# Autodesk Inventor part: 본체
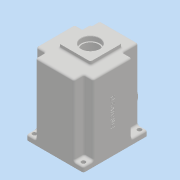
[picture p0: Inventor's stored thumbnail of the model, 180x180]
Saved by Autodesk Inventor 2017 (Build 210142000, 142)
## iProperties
Part Number: 본체
Material: 일반
Document SubType Name: Modeling
Designer: MRC
Density: 1 g/cm^3
Appearance: 기본값
Author: MRC
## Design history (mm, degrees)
sketch "스케치1"
  geometry: L1 (-49, -55)-(49, -55); L2 (49, -55)-(49, 55); L3 (49, 55)-(-49, 55); L4 (-49, 55)-(-49, -55); 3 further points
  constraints: 8 end point, 2 midpoint, 2 parallel, 1 horizontal, 1 horizontal alignment, 1 perpendicular, 1 vertical alignment
  dimensions: "d11" = 98 distance of L2.end L3.end; "d12" = 110 distance of L3.end L1.start
extrude "돌출1" new body sketch "스케치1" distance "d13" = 130; taper "d14" = 0 deg
sketch "스케치2"
  geometry: L1 (33, 28)-(49, 28); L2 (49, 28)-(49, 55); L3 (49, 55)-(33, 55); L4 (33, 55)-(33, 28); L5 (-49, 28)-(-33, 28); L6 (-33, 28)-(-33, 55); L7 (-33, 55)-(-49, 55); L8 (-49, 55)-(-49, 28); 3 further points
  constraints: 16 end point, 4 parallel, 2 coincident, 2 horizontal, 2 perpendicular
  dimensions: "d15" = 16 distance of L2.end L3.end; "d16" = 27 distance of L3.end L1.start; "d17" = 16 distance of L6.end L7.end; "d18" = 27 distance of L7.end L5.start
extrude "돌출2" cut sketch "스케치2" distance "d19" = 121; taper "d20" = 0 deg
sketch "스케치3"
  geometry: L1 (33, -55)-(49, -55); L2 (49, -55)-(49, -38); L3 (49, -38)-(33, -38); L4 (33, -38)-(33, -55); L5 (-49, -55)-(-33, -55); L6 (-33, -55)-(-33, -38); L7 (-33, -38)-(-49, -38); L8 (-49, -38)-(-49, -55); 3 further points
  constraints: 16 end point, 4 parallel, 2 coincident, 2 horizontal, 2 perpendicular
  dimensions: "d21" = 17 distance of L1.end L2.end; "d22" = 17 distance of L5.end L6.end; "d23" = 16 distance of L2.end L3.end; "d24" = 16 distance of L6.end L7.end
extrude "돌출3" cut sketch "스케치3" distance "d25" = 121; taper "d26" = 0 deg
fillet "모깎기1" dims "d27" = 3
sketch "스케치5"
  geometry: L1 (-20, 45)-(20, 45); L2 (23, 42)-(23, 33.249); L3 (-23, 33.249)-(-23, 42); L4 (46, -55)-(-46, -55) reference; L5 (-26, 42)-(-26, 33.249); L6 (26, 33.249)-(26, 42); L7 (20, 48)-(-20, 48); A1 r 42 centre (0, -5) between (-25.375, 28.468) and (25.375, 28.468); A2 r 6 centre (-29, 33.249) between (-25.375, 28.468) and (-23, 33.249); A3 r 6 centre (29, 33.249) between (23, 33.249) and (25.375, 28.468); A4 r 3 centre (-20, 42) between (-20, 45) and (-23, 42); A5 r 3 centre (20, 42) between (23, 42) and (20, 45); A6 r 3 centre (-29, 33.249) between (-27.187, 30.859) and (-26, 33.249); A7 r 45 centre (0, -5) between (-27.187, 30.859) and (27.187, 30.859); A8 r 3 centre (29, 33.249) between (26, 33.249) and (27.187, 30.859); A9 r 6 centre (20, 42) between (26, 42) and (20, 48); A10 r 6 centre (-20, 42) between (-20, 48) and (-26, 42); 6 further points
  constraints: 22 point on circle, 12 end point, 10 centre point, 8 tangent, 6 point on line, 2 equal radius, 2 parallel, 2 perpendicular, 2 vertical alignment, 1 horizontal, 1 midpoint, 7 other
  dimensions: "d39" = 46 distance of point (-23, 45) point (23, 45); "d40" = 84 diameter of A1; "d41" = 50 distance from line of L4 A1.centre; "d42" = 50 distance from line of L1 A1.centre; "d43" = 6 radius of A2 (derived); "d44" = 3 radius of A4 (derived); "d47" = 3 distance between parallel lines of L3 L5
extrude "돌출6" cut sketch "스케치5" distance "d45" = 121; taper "d46" = 0 deg
extrude "돌출7" cut sketch "스케치5" distance "d48" = 9; taper "d49" = 0 deg
sketch "스케치6"
  geometry: C1 r 21 at (0, 6); C2 r 15 at (0, -25); A1 r 42 centre (0, -5) between (-25.375, 28.468) and (25.375, 28.468) reference; 1 further point
  constraints: 2 centre point, 2 vertical alignment
  dimensions: "d50" = 11 distance of C1.centre A1.centre; "d51" = 20 distance of C2.centre A1.centre; "d52" = 42 diameter of C1; "d53" = 30 diameter of C2
extrude "돌출8" join sketch "스케치6" distance "d54" = 7; taper "d55" = 0 deg
fillet "모깎기2" dims "d56" = 3
sketch "스케치9"
  geometry: L1 (-24, -21)-(24, -21); L2 (27, -18)-(27, 30); L3 (24, 33)-(-24, 33); L4 (-27, 30)-(-27, -18); A1 r 21 centre (0, 6) between (12.163, -11.119) and (-12.163, -11.119) reference; A2 r 3 centre (-24, 30) between (-24, 33) and (-27, 30); A3 r 3 centre (24, 30) between (27, 30) and (24, 33); A4 r 3 centre (24, -18) between (24, -21) and (27, -18); A5 r 3 centre (-24, -18) between (-27, -18) and (-24, -21); 6 further points
  constraints: 8 end point, 8 point on circle, 8 tangent, 6 point on line, 4 centre point, 3 equal radius, 2 midpoint, 2 parallel, 1 horizontal, 1 horizontal alignment, 1 perpendicular, 1 vertical alignment
  dimensions: "d63" = 54 distance of point (27, 33) point (-27, 33); "d64" = 54 distance of point (-27, 33) point (-27, -21); "d65" = 3 radius of A2 (derived)
extrude "돌출10" join sketch "스케치9" distance "d66" = 7; taper "d67" = 0 deg
fillet "모깎기4" dims "d68" = 3
sketch "스케치10"
  geometry: C1 r 16 at (0, 6); A1 r 21 centre (0, 6) between (12.163, -11.119) and (-12.163, -11.119) reference; 1 further point
  constraints: 1 centre point, 1 coincident
  dimensions: "d69" = 32 diameter of C1
extrude "돌출11" cut sketch "스케치10" distance "d70" = 8.3; taper "d71" = 0 deg
sketch "스케치11"
  geometry: C1 r 17.5 at (0, 6); A1 r 21 centre (0, 6) between (12.163, -11.119) and (-12.163, -11.119) reference; 1 further point
  constraints: 1 centre point, 1 coincident
  dimensions: "d72" = 35 diameter of C1
extrude "돌출12" cut sketch "스케치11" distance "d73" = 10; taper "d74" = 0 deg
sketch "스케치12"
  geometry: C1 r 17.5 at (0, 0) reference; C2 r 14 at (0, 0); 1 further point
  constraints: 1 centre point, 1 coincident
  dimensions: "d75" = 28 diameter of C2
extrude "돌출13" cut sketch "스케치12" stored distance "d76" = 10; taper "d77" = 0 deg
sketch "스케치13"
  geometry: L1 (22.462, 137)-(22, 136.2); L2 (22, 136.2)-(22, 137); L3 (22, 137)-(22.462, 137); L4 (22, 137)-(22, 128.7) reference; L5 (-10, 137)-(22, 137) reference; L6 (6, 137)-(6, 114); L7 (23.5, 114)-(-11.5, 114) reference; 1 further point
  constraints: 8 end point, 2 midpoint, 1 perpendicular, 1 vertical
  dimensions: "d78" = 30 deg angle of L2 L1; "d79" = 0.8 distance of L2.end L1.end
revolve "회전1" sketch "스케치13" stored, may be unused: angle "d80" = 90 deg
fillet "모깎기5" dims "d81" = 0.3
hole "구멍1" diameter "d84" = 19; stored, may be unused: countersink angle "d88" = 90 deg, drill point angle "d90" = 0 deg; dims "d82" = 10, "d83" = 10, "d85" = 6, "d86" = 22, "d87" = 7, "d89" = 10
fillet "모깎기6" dims "d91" = 3
fillet "모깎기7" dims "d92" = 0.3
fillet "모깎기8" dims "d93" = 3
sketch "스케치15"
  geometry: L1 (92, 0)-(0, 0) reference; C1 r 22.5 at (46, -40); 2 further points
  constraints: 1 centre point, 1 midpoint, 1 vertical alignment
  dimensions: "d94" = 45 diameter of C1; "d95" = 40 distance of point (46, 0) C1.centre
extrude "돌출14" join sketch "스케치15" distance "d96" = 10; taper "d97" = 0 deg
sketch "스케치16"
  geometry: L1 (92, 0)-(0, 0) reference; C1 r 15 at (46, -89); 2 further points
  constraints: 1 centre point, 1 midpoint, 1 vertical alignment
  dimensions: "d98" = 30 diameter of C1; "d99" = 89 distance of C1.centre point (46, 0)
extrude "돌출15" join sketch "스케치16" distance "d100" = 5; taper "d101" = 0 deg
sketch "스케치17"
  geometry: C1 r 15 at (20, -32) reference; 2 further points
  constraints: 1 coincident
hole "구멍2" sketch "스케치17" at (20, -32) diameter "d102" = 20; stored, may be unused: countersink angle "d106" = 90 deg, drill point angle "d108" = 0 deg; dims "d103" = 6, "d104" = 30, "d105" = 5, "d107" = 10
hole "구멍3" diameter "d111" = 33.376; stored, may be unused: countersink angle "d115" = 90 deg, drill point angle "d117" = 0 deg; dims "d109" = 10, "d110" = 10, "d112" = 70, "d113" = 30, "d114" = 5, "d116" = 77.3
fillet "모깎기9" dims "d118" = 3
chamfer "모따기1" distance "d119" = 1; stored, may be unused: second distance "d120" = 2, angle "d121" = 45 deg
fillet "모깎기10" dims "d122" = 3
sketch "스케치18"
  geometry: L1 (-46, 55)-(46, 55) reference; L2 (-49, -52)-(-49, 52) reference; L3 (0, 0)-(0, 8.024); L4 (0, 0)-(-4.182, 0); C1 r 3.5 at (-42, 48); C2 r 3.5 at (42, 48); C3 r 3.5 at (42, -48); C4 r 3.5 at (-42, -48)
  constraints: 4 centre point, 4 end point, 3 symmetric about line, 1 horizontal, 1 vertical, 3 other
  dimensions: "d123" = 7 diameter of C1; "d124" = 7 distance from line of L1 C1.centre; "d125" = 7 distance from line of L2 C1.centre
extrude "돌출16" cut sketch "스케치18" distance "d126" = 10; taper "d127" = 0 deg
sketch "스케치19"
  geometry: L1 (35.777, -1)-(41.809, -1); L2 (35.777, -9)-(41.809, -9); A1 r 42 centre (0, -5) between (-25.375, 28.468) and (25.375, 28.468) reference; A2 r 36 centre (0, -5) between (36, -5) and (35.777, -9); A3 r 4 centre (36, -5) between (36, -1) and (36, -9); 1 further point
  constraints: 7 point on circle, 4 end point, 2 centre point, 2 horizontal, 2 point on line, 2 tangent, 1 coincident, 1 horizontal alignment
  dimensions: "d128" = 72 diameter of A2; "d129" = 8 diameter of A3
extrude "돌출17" join sketch "스케치19" stored distance "d130" = 10; taper "d131" = 0 deg
fillet "모깎기11" dims "d132" = 3
hole "구멍4" diameter "d135" = 3.242; stored, may be unused: countersink angle "d139" = 90 deg, drill point angle "d141" = 118 deg; dims "d136" = 7, "d137" = 30, "d138" = 5, "d140" = 9, "d142" = 10, "d143" = 10
sketch "스케치20"
  geometry: L1 (-130, 104)-(-130, 83) reference; L2 (-12, 80)-(-127, 80) reference; 2 further points
  constraints: 1 other
  dimensions: "d144" = 65 distance from line of L1 point (-65, 47); "d145" = 33 distance from line of point (-65, 47) L2
feature "엠보싱1" sketch "스케치20" dims "d146" = 0.5, "d147" = 0
node "솔리드1"
mirror "미러1"
node "작업 평면1"
